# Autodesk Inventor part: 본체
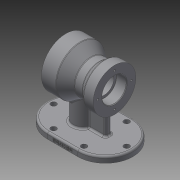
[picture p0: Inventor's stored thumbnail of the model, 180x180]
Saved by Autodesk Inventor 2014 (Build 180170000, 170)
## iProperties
Created: 2020-01
Part Number: 본체
Material: Generic
Document SubType Name: Modeling
Designer: kh
Density: 1 g/cm^3
Appearance: Default
Author: kh
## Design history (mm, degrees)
sketch "Sketch3"
  geometry: L1 (-25, -45)-(25, -45); L2 (70, 0)-(70, 0); L3 (25, 45)-(-25, 45); L4 (-70, 0)-(-70, 0); L5 (-70, -45)-(70, 45); L6 (70, -45)-(-70, 45); A1 r 45 centre (-25, 0) between (-25, 45) and (-70, 0); A2 r 45 centre (-25, 0) between (-70, 0) and (-25, -45); A3 r 45 centre (25, 0) between (25, -45) and (70, 0); A4 r 45 centre (25, 0) between (70, 0) and (25, 45); 1 further point
  constraints: 12 end point, 8 point on circle, 8 point on line, 8 tangent, 4 centre point, 3 equal radius, 2 midpoint, 2 parallel, 1 horizontal, 1 perpendicular
  dimensions: "d4" = 140 distance of L5.end L6.end; "d5" = 90 distance of L6.start L5.end; "d6" = 45 radius of A1; "d7" = 50 distance of A3.centre A1.centre (derived)
extrude "Extrusion2" new body sketch "Sketch3" distance "d8" = 10; taper "d9" = 0 deg
sketch "Sketch4"
  geometry: C1 r 16 at (-12, 0); A1 r 45 centre (-25, 0) between (-25, 45) and (-25, -45) reference; 2 further points
  constraints: 1 centre point, 1 horizontal alignment, 1 point on circle
  dimensions: "d10" = 32 diameter of C1; "d11" = 58 distance of point (-70, 0) C1.centre
extrude "Extrusion3" join sketch "Sketch4" distance "d12" = 70; taper "d13" = 0 deg
sketch "Sketch5"
  geometry: L1 (-40, 80)-(67.661, 80); L2 (40, 80)-(40, 120); L3 (40, 120)-(16, 120); L4 (16, 120)-(-1.852, 107.5); L5 (-1.852, 107.5)-(-15.062, 107.5); L6 (-15.062, 107.5)-(-24, 115); L7 (-24, 115)-(-40, 115); L8 (-40, 115)-(-40, 80); L9 (70, 0)-(70, 10) reference; 1 further point
  constraints: 16 end point, 3 parallel, 2 perpendicular, 1 horizontal, 1 point on line
  dimensions: "d14" = 80 distance from line of point (0, 0) L1; "d15" = 80 diameter of L3 L1; "d16" = 70 diameter of L7 L1; "d17" = 16 distance of L6.end L7.end; "d18" = 24 distance of L2.end L3.end; "d19" = 80 distance between parallel lines of L8 L2; "d20" = 35 deg angle of L4 L5; "d21" = 40 deg angle of L5 L6; "d22" = 30 distance between parallel lines of L9 L2; "d23" = 55 diameter of L5 L1
revolve "Revolution1" sketch "Sketch5" stored, may be unused: angle "d24" = 90 deg
sketch "Sketch6"
  geometry: L1 (-30, 68.236)-(-30, 5.842); L2 (-40, 45)-(-40, 115) reference; L3 (-4, 10)-(-4, 52.5) reference; 1 further point
  constraints: 2 end point, 1 vertical
  dimensions: "d25" = 10 distance between parallel lines of L2 L1
feature "Rib1" sketch "Sketch6" dims "d26" = 1, "d27" = 10, "d28" = 0, "d29" = 0, "d30" = 1, "d31" = 1
sketch "Sketch7"
  geometry: L1 (-40, 45)-(-40, 115) reference; L2 (40, 40)-(40, 120) reference; L3 (40, 80)-(-40, 80); L4 (40, 80)-(40, 106); L5 (40, 106)-(20.3, 106); L6 (20, 105.7)-(20, 96); L7 (20, 96)-(-23, 96); L8 (-23, 96)-(-23, 99.7); L9 (-23.3, 100)-(-40, 100); L10 (-40, 100)-(-40, 80); A1 r 0.3 centre (-23.3, 99.7) between (-23, 99.7) and (-23.3, 100); A2 r 0.3 centre (20.3, 105.7) between (20.3, 106) and (20, 105.7); 3 further points
  constraints: 16 end point, 6 point on line, 4 point on circle, 4 tangent, 3 perpendicular, 2 centre point, 2 midpoint, 2 parallel, 1 collinear, 1 equal radius
  dimensions: "d32" = 52 diameter of L5 L3; "d33" = 32 diameter of L7 L3; "d34" = 40 diameter of L9 L3; "d35" = 20 distance of L4.end point (20, 106); "d36" = 17 distance of point (-23, 100) L9.end; "d37" = 0.3 radius of A1
revolve "Revolution2" sketch "Sketch7" stored, may be unused: angle "d38" = 90 deg
sketch "Sketch8"
  geometry: C1 r 20 at (0, 0) reference; 2 further points
  constraints: 1 horizontal alignment
  dimensions: "d39" = 27.5 distance of C1.centre point (-27.5, 0)
hole "Hole1" sketch "Sketch8" at (-27.5, 0) diameter "d40" = 3.242; stored, may be unused: countersink angle "d44" = 90 deg, drill point angle "d46" = 118 deg; dims "d41" = 9, "d42" = 4, "d43" = 2, "d45" = 11
pattern_circular "Circular Pattern1" dims angle "d48" = 360 deg
sketch "Sketch9"
  geometry: C1 r 26 at (0, 0) reference; 2 further points
  constraints: 1 horizontal alignment
  dimensions: "d50" = 33 distance of C1.centre point (33, 0)
hole "Hole2" sketch "Sketch9" at (33, 0) diameter "d51" = 3.242; stored, may be unused: countersink angle "d55" = 90 deg, drill point angle "d57" = 118 deg; dims "d52" = 9, "d53" = 4, "d54" = 2, "d56" = 11
pattern_circular "Circular Pattern2" dims angle "d59" = 360 deg
sketch "Sketch10"
  geometry: L1 (25, 45)-(-25, 45) reference; L2 (30, -5)-(3.199, -5) reference; L3 (-25, 0)-(25, 0); L4 (-25, -35)-(25, -35); L5 (25, 35)-(-25, 35); A1 r 45 centre (-25, 0) between (-25, 45) and (-25, -45) reference; A2 r 45 centre (25, 0) between (25, -45) and (25, 45) reference; A3 r 35 centre (-25, 0) between (-25, 35) and (-25, -35); A4 r 35 centre (25, 0) between (25, -35) and (25, 35); 8 further points
  constraints: 8 end point, 8 point on circle, 4 tangent, 2 centre point, 2 parallel, 2 vertical alignment, 1 coincident, 1 midpoint, 1 point on line
  dimensions: "d61" = 10 distance between parallel lines of L5 L1; "d62" = 50 distance of point (25, 35) point (-25, 35)
hole "Hole3" sketch "Sketch10" at (-60, 0), (60, 0), (-25, 35), (25, 35), (25, -35), (-25, -35) diameter "d63" = 9; stored, may be unused: countersink angle "d67" = 90 deg, drill point angle "d69" = 118 deg; dims "d64" = 9, "d65" = 4, "d66" = 2, "d68" = 12
sketch "Sketch11"
  geometry: L1 (-45, 0)-(-45, 10) reference; 2 further points
  constraints: 1 other
  dimensions: "d70" = 70 distance from line of L1 point (25, 4); "d71" = 4 distance of point (25, 0) point (25, 4)
emboss "Emboss1" sketch "Sketch11" dims "d4" = 140, "d5" = 90, "d6" = 45, "d7" = 50 (derived), "d72" = 0.5, "d73" = 0
fillet "Fillet1" dims "d74" = 3, "d75" = 3, "d76" = 2
chamfer "Chamfer1" distance "d77" = 1; stored, may be unused: second distance "d78" = 2, angle "d79" = 45 deg
body "Solid2"
